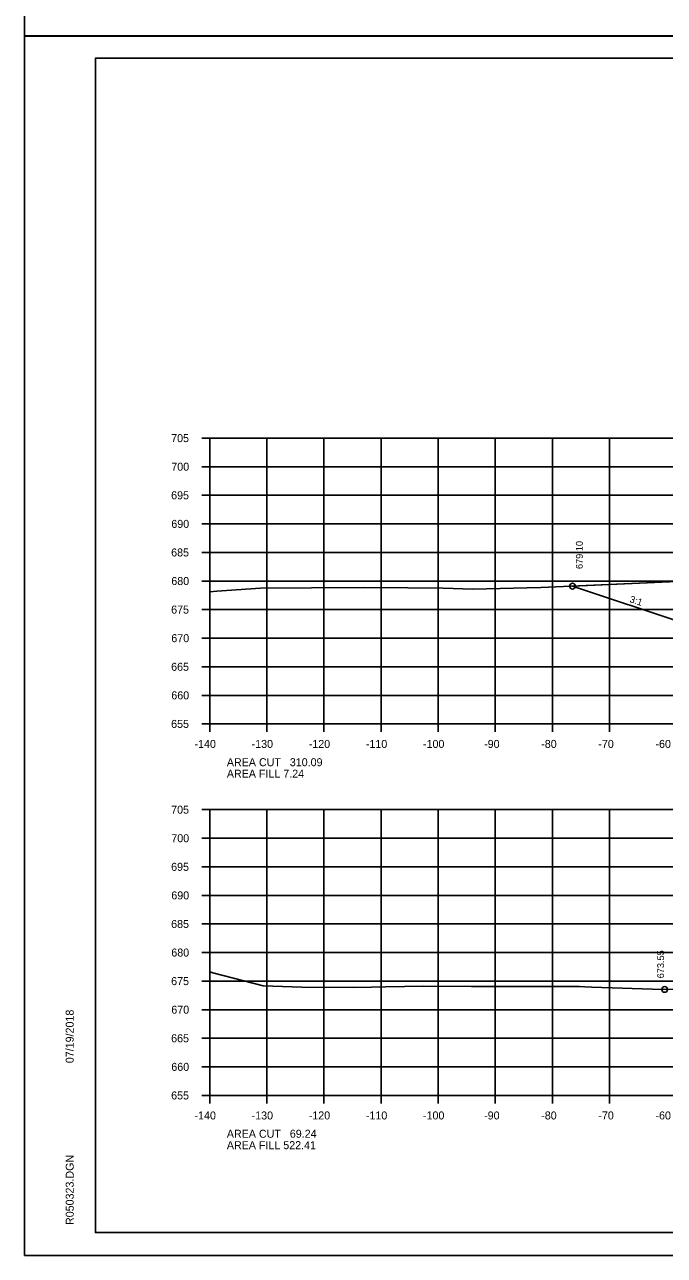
# Model space of a CAD drawing. Extents: x 1360146 to 1361431, y 631444 to 632352.
# Drawn here: x 1360146.4 to 1360258.4, y 631870.8 to 632086.2 of the extents above; entities that cross this region are included whole.
import ezdxf

# ---------------------------------------------------------------- set-up
doc = ezdxf.new("R2010")
doc.units = 0
for name, color, linetype in [('R_Axis', 7, 'Continuous'), ('R_Axis Annot', 7, 'Continuous'), ('R_Border', 7, 'Continuous'), ('R_Exist Surface', 7, 'Continuous'), ('R_Fin Surface', 7, 'Continuous'), ('R_Grid', 7, 'Continuous'), ('R_No Plot', 7, 'Continuous'), ('R_Xsect Elev', 7, 'Continuous'), ('R_Xsect Slope', 7, 'Continuous')]:
    doc.layers.add(name, color=color, linetype=linetype)

msp = doc.modelspace()

# ---------------------------------------------------------------- linework, layer by layer
at = {"layer": 'R_Axis'}
for p, q in [((1360177.37, 632013.82), (1360178.77, 632013.82)), ((1360178.77, 631963.82), (1360178.77, 632013.82)), ((1360177.37, 632008.82), (1360178.77, 632008.82)), ((1360177.37, 632003.82), (1360178.77, 632003.82)), ((1360177.37, 631998.82), (1360178.77, 631998.82)), ((1360177.37, 631993.82), (1360178.77, 631993.82)), ((1360177.37, 631988.82), (1360178.77, 631988.82)), ((1360177.37, 631983.82), (1360178.77, 631983.82)), ((1360177.37, 631978.82), (1360178.77, 631978.82)), ((1360177.37, 631973.82), (1360178.77, 631973.82)), ((1360177.37, 631968.82), (1360178.77, 631968.82)), ((1360177.37, 631963.82), (1360178.77, 631963.82)), ((1360178.77, 631963.82), (1360458.77, 631963.82)), ((1360178.77, 631962.42), (1360178.77, 631963.82)), ((1360188.77, 631962.42), (1360188.77, 631963.82)), ((1360198.77, 631962.42), (1360198.77, 631963.82)), ((1360208.77, 631962.42), (1360208.77, 631963.82)), ((1360218.77, 631962.42), (1360218.77, 631963.82)), ((1360228.77, 631962.42), (1360228.77, 631963.82)), ((1360238.77, 631962.42), (1360238.77, 631963.82)), ((1360248.77, 631962.42), (1360248.77, 631963.82)), ((1360177.37, 631948.82), (1360178.77, 631948.82)), ((1360178.77, 631898.82), (1360178.77, 631948.82)), ((1360177.37, 631943.82), (1360178.77, 631943.82)), ((1360177.37, 631938.82), (1360178.77, 631938.82)), ((1360177.37, 631933.82), (1360178.77, 631933.82)), ((1360177.37, 631928.82), (1360178.77, 631928.82)), ((1360177.37, 631923.82), (1360178.77, 631923.82)), ((1360177.37, 631918.82), (1360178.77, 631918.82)), ((1360177.37, 631913.82), (1360178.77, 631913.82)), ((1360177.37, 631908.82), (1360178.77, 631908.82)), ((1360177.37, 631903.82), (1360178.77, 631903.82)), ((1360177.37, 631898.82), (1360178.77, 631898.82)), ((1360178.77, 631898.82), (1360458.77, 631898.82)), ((1360178.77, 631897.42), (1360178.77, 631898.82)), ((1360188.77, 631897.42), (1360188.77, 631898.82)), ((1360198.77, 631897.42), (1360198.77, 631898.82)), ((1360208.77, 631897.42), (1360208.77, 631898.82)), ((1360218.77, 631897.42), (1360218.77, 631898.82)), ((1360228.77, 631897.42), (1360228.77, 631898.82)), ((1360238.77, 631897.42), (1360238.77, 631898.82)), ((1360248.77, 631897.42), (1360248.77, 631898.82))]:
    msp.add_line(p, q, dxfattribs=at)
at = {"layer": 'R_Border'}
for p, q in [((1360158.77, 632080.28), (1360474.95, 632080.28)), ((1360158.77, 631874.82), (1360158.77, 632080.28)), ((1360158.77, 631874.82), (1360158.77, 631874.82)), ((1360474.95, 631874.82), (1360158.77, 631874.82))]:
    msp.add_line(p, q, dxfattribs=at)
at = {"layer": 'R_Exist Surface'}
for points in [[(1360178.77, 631986.94), (1360180.02, 631987.07), (1360187.65, 631987.57), (1360196.62, 631987.63), (1360205.79, 631987.7), (1360213.48, 631987.62), (1360219.66, 631987.56), (1360224.86, 631987.38), (1360236.74, 631987.68), (1360260.53, 631988.72)], [(1360178.77, 631920.44), (1360179.34, 631920.25), (1360188.15, 631917.99), (1360194.91, 631917.79), (1360203.98, 631917.69), (1360207.07, 631917.74), (1360209.54, 631917.8), (1360216.21, 631917.93), (1360224.58, 631917.89), (1360242.29, 631917.86), (1360243.5, 631917.86), (1360244.47, 631917.84), (1360245.65, 631917.77), (1360258.06, 631917.36), (1360264.29, 631917.44)]]:
    msp.add_lwpolyline(points, dxfattribs=at)
at = {"layer": 'R_Fin Surface'}
msp.add_lwpolyline([(1360242.28, 631987.92), (1360261.78, 631981.42), (1360298.75, 631993.74), (1360298.77, 631993.75), (1360304.77, 631995.25), (1360308.77, 631994.95), (1360318.77, 631994.19), (1360328.77, 631993.42), (1360332.77, 631993.12), (1360338.55, 631991.67), (1360338.77, 631991.62), (1360365.47, 631982.72), (1360384.22, 631988.97)], dxfattribs=at)
at = {"layer": 'R_Grid'}
for p, q in [((1360178.77, 632013.82), (1360458.77, 632013.82)), ((1360178.77, 631963.82), (1360178.77, 632013.82)), ((1360188.77, 631963.82), (1360188.77, 632013.82)), ((1360198.77, 631963.82), (1360198.77, 632013.82)), ((1360208.77, 631963.82), (1360208.77, 632013.82)), ((1360218.77, 631963.82), (1360218.77, 632013.82)), ((1360228.77, 631963.82), (1360228.77, 632013.82)), ((1360238.77, 631963.82), (1360238.77, 632013.82)), ((1360248.77, 631963.82), (1360248.77, 632013.82)), ((1360178.77, 632008.82), (1360458.77, 632008.82)), ((1360178.77, 632003.82), (1360458.77, 632003.82)), ((1360178.77, 631998.82), (1360458.77, 631998.82)), ((1360178.77, 631993.82), (1360458.77, 631993.82)), ((1360178.77, 631988.82), (1360458.77, 631988.82)), ((1360178.77, 631983.82), (1360458.77, 631983.82)), ((1360178.77, 631978.82), (1360458.77, 631978.82)), ((1360178.77, 631973.82), (1360458.77, 631973.82)), ((1360178.77, 631968.82), (1360458.77, 631968.82)), ((1360178.77, 631963.82), (1360458.77, 631963.82)), ((1360178.77, 631948.82), (1360458.77, 631948.82)), ((1360178.77, 631898.82), (1360178.77, 631948.82)), ((1360188.77, 631898.82), (1360188.77, 631948.82)), ((1360198.77, 631898.82), (1360198.77, 631948.82)), ((1360208.77, 631898.82), (1360208.77, 631948.82)), ((1360218.77, 631898.82), (1360218.77, 631948.82)), ((1360228.77, 631898.82), (1360228.77, 631948.82)), ((1360238.77, 631898.82), (1360238.77, 631948.82)), ((1360248.77, 631898.82), (1360248.77, 631948.82)), ((1360178.77, 631943.82), (1360458.77, 631943.82)), ((1360178.77, 631938.82), (1360458.77, 631938.82)), ((1360178.77, 631933.82), (1360458.77, 631933.82)), ((1360178.77, 631928.82), (1360458.77, 631928.82)), ((1360178.77, 631923.82), (1360458.77, 631923.82)), ((1360178.77, 631918.82), (1360458.77, 631918.82)), ((1360178.77, 631913.82), (1360458.77, 631913.82)), ((1360178.77, 631908.82), (1360458.77, 631908.82)), ((1360178.77, 631903.82), (1360458.77, 631903.82)), ((1360178.77, 631898.82), (1360458.77, 631898.82))]:
    msp.add_line(p, q, dxfattribs=at)
at = {"layer": 'R_No Plot'}
for p, q in [((1360146.37, 632084.18), (1360479.7, 632084.18)), ((1360146.37, 632084.17), (1360479.7, 632084.17)), ((1360146.37, 631870.84), (1360479.7, 631870.84))]:
    msp.add_line(p, q, dxfattribs=at)
for points in [[(1360146.36, 632297.51), (1360479.7, 632297.51), (1360479.7, 632084.17), (1360146.36, 632084.17)], [(1360146.36, 632084.17), (1360479.7, 632084.17), (1360479.7, 631870.84), (1360146.36, 631870.84)], [(1360392.69, 632080.28), (1360392.69, 632070.4), (1360428.42, 632070.4), (1360428.42, 632067.48), (1360451.62, 632067.48), (1360451.62, 632043.15), (1360474.95, 632043.15), (1360474.95, 631874.82), (1360158.77, 631874.82), (1360158.77, 632080.28)], [(1360242.28, 631987.92), (1360260.53, 631988.72), (1360260.57, 631988.72), (1360260.61, 631988.72), (1360266.15, 631988.93), (1360279.32, 631989.69), (1360283.36, 631989.88), (1360288.84, 631990.44), (1360261.78, 631981.42)]]:
    msp.add_lwpolyline(points, close=True, dxfattribs=at)
for centre in [(1360242.28, 631987.92), (1360258.42, 631917.36)]:
    msp.add_circle(centre, 0.5, dxfattribs=at)

# ---------------------------------------------------------------- texts
at = {"layer": 'R_Axis Annot'}
for s, p in [('705', (1360172.02, 632013.12)), ('700', (1360172.05, 632008.12)), ('695', (1360172.02, 632003.12)), ('690', (1360172.05, 631998.12)), ('685', (1360172.02, 631993.12)), ('680', (1360172.05, 631988.12)), ('675', (1360172.02, 631983.12)), ('670', (1360172.05, 631978.12)), ('665', (1360172.02, 631973.12)), ('660', (1360172.05, 631968.12)), ('655', (1360172.02, 631963.12)), ('-140', (1360176.11, 631959.62)), ('-130', (1360186.11, 631959.62)), ('-120', (1360196.11, 631959.62)), ('-110', (1360206.11, 631959.62)), ('-100', (1360216.11, 631959.62)), ('-90', (1360226.81, 631959.62)), ('-80', (1360236.81, 631959.62)), ('-70', (1360246.81, 631959.62)), ('-60', (1360256.81, 631959.62)), ('AREA CUT   310.09', (1360181.77, 631956.42)), ('AREA FILL 7.24', (1360181.77, 631954.42)), ('705', (1360172.02, 631948.12)), ('700', (1360172.05, 631943.12)), ('695', (1360172.02, 631938.12)), ('690', (1360172.05, 631933.12)), ('685', (1360172.02, 631928.12)), ('680', (1360172.05, 631923.12)), ('675', (1360172.02, 631918.12)), ('670', (1360172.05, 631913.12)), ('665', (1360172.02, 631908.12)), ('660', (1360172.05, 631903.12)), ('655', (1360172.02, 631898.12)), ('-140', (1360176.11, 631894.62)), ('-130', (1360186.11, 631894.62)), ('-120', (1360196.11, 631894.62)), ('-110', (1360206.11, 631894.62)), ('-100', (1360216.11, 631894.62)), ('-90', (1360226.81, 631894.62)), ('-80', (1360236.81, 631894.62)), ('-70', (1360246.81, 631894.62)), ('-60', (1360256.81, 631894.62)), ('AREA CUT   69.24', (1360181.77, 631891.42)), ('AREA FILL 522.41', (1360181.77, 631889.42))]:
    msp.add_text(s, height=1.4, dxfattribs=at).set_placement(p)
at = {"layer": 'R_Border'}
for s, p in [('07/19/2018', (1360154.96, 631904.46)), ('R050323.DGN', (1360154.96, 631876.15))]:
    msp.add_text(s, height=1.4, rotation=90, dxfattribs=at).set_placement(p)
at = {"layer": 'R_Xsect Elev'}
for s, p in [('679.10', (1360244.08, 631990.92)), ('673.55', (1360258.31, 631919.31))]:
    msp.add_text(s, height=1.2, rotation=90, dxfattribs=at).set_placement(p)
at = {"layer": 'R_Xsect Slope'}
msp.add_text('3:1', height=1.2, rotation=341.5651, dxfattribs=at).set_placement((1360252.19, 631985.15))

doc.saveas('drawing.dxf')
